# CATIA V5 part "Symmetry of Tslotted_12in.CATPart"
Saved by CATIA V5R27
Part number: Symmetry of Tslotted_12in
Bounding box of the stored display mesh (mm): x -19.056 to 19.056, y -19.056 to 19.056, z -1524 to -1216.66
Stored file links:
  \\triton.meca.polymtl.ca\usagers\zaoue\profiles\Desktop\varm_ass\structure prismatique\Symmetry of Tslotted_12in.CATPart
  \\triton.meca.polymtl.ca\usagers\zaoue\profiles\Desktop\varm_ass\bearing assy\Alu_Tslot_12in.CATPart
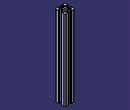
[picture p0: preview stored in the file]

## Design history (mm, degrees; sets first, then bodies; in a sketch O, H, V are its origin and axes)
Body1 (main body)
  Body2 "Corps du corps principal d'origine"
    Solid1: linked copy from another document
  Assemble1: tool Body2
